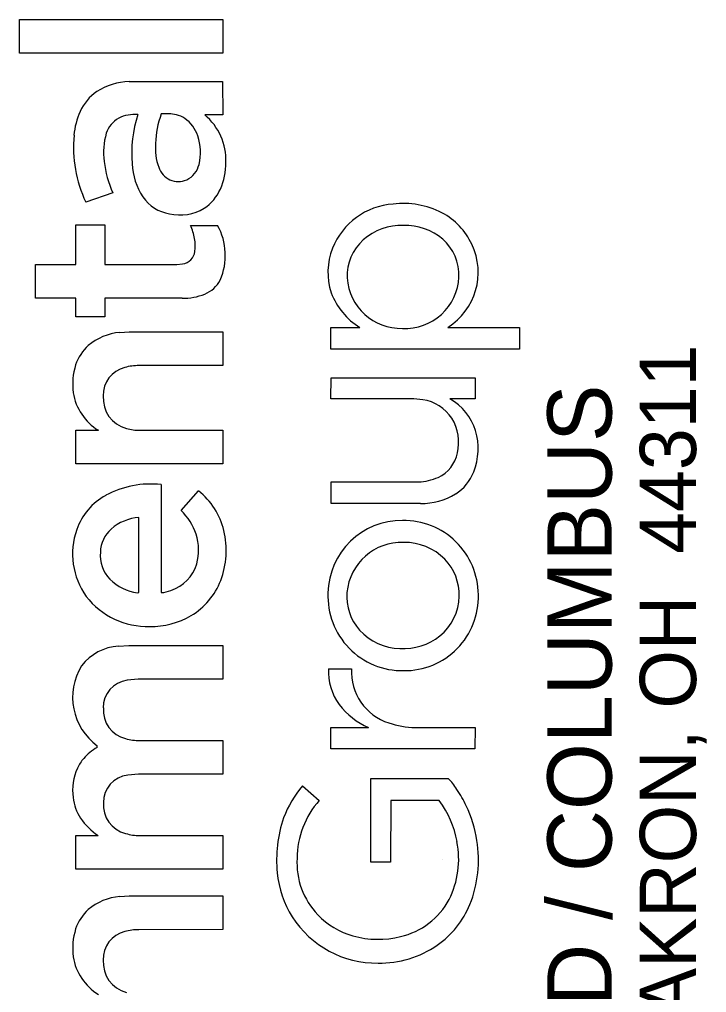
# Model space of a CAD drawing. Extents: x -0.2 to 34, y 0 to 22.
# Drawn here: x 32.376 to 32.984, y 3.882 to 4.744 of the extents above; entities that cross this region are included whole.
import ezdxf

# ---------------------------------------------------------------- set-up
doc = ezdxf.new("R2010")
doc.units = 0
doc.layers.add('RW_X_Esmt_SH', color=7, linetype='Continuous')

msp = doc.modelspace()

# ---------------------------------------------------------------- linework, layer by layer
at = {"layer": 'RW_X_Esmt_SH'}
for p, q in [((32.37557, 4.71411), (32.37557, 4.74397)), ((32.37557, 4.74397), (32.55571, 4.74397)), ((32.55571, 4.74397), (32.55571, 4.71411)), ((32.55571, 4.71411), (32.37557, 4.71411)), ((32.47265, 4.68899), (32.55553, 4.68918)), ((32.55553, 4.68918), (32.55571, 4.65956)), ((32.55571, 4.65956), (32.53971, 4.65956)), ((32.45818, 4.59045), (32.43431, 4.58233)), ((32.42542, 4.52705), (32.42548, 4.56209)), ((32.42548, 4.56209), (32.45108, 4.56209)), ((32.45108, 4.56209), (32.45117, 4.52705)), ((32.52695, 4.56159), (32.5511, 4.56159)), ((32.38964, 4.52701), (32.42542, 4.52705)), ((32.38964, 4.49719), (32.38964, 4.52701)), ((32.45117, 4.52705), (32.51498, 4.52705)), ((32.51498, 4.52705), (32.52005, 4.52749)), ((32.42542, 4.49717), (32.38964, 4.49719)), ((32.42542, 4.48067), (32.42542, 4.49717)), ((32.51969, 4.49718), (32.45108, 4.49715)), ((32.45108, 4.49715), (32.45108, 4.48066)), ((32.45108, 4.48066), (32.42542, 4.48067)), ((32.46439, 4.46686), (32.47289, 4.46732)), ((32.47289, 4.46732), (32.55571, 4.46732)), ((32.55571, 4.46732), (32.55571, 4.43753)), ((32.65152, 4.47113), (32.67709, 4.47115)), ((32.65152, 4.45215), (32.65152, 4.47113)), ((32.75491, 4.47132), (32.81858, 4.47108)), ((32.81858, 4.47108), (32.81843, 4.45215)), ((32.81843, 4.45215), (32.65152, 4.45215)), ((32.55571, 4.43753), (32.4814, 4.43746)), ((32.65152, 4.40801), (32.65153, 4.42672)), ((32.65153, 4.42672), (32.7791, 4.42664)), ((32.7791, 4.42664), (32.77908, 4.40796)), ((32.7249, 4.40796), (32.65152, 4.40801)), ((32.7328, 4.40727), (32.7249, 4.40796)), ((32.77908, 4.40796), (32.75689, 4.40796)), ((32.42542, 4.38016), (32.44552, 4.38021)), ((32.42542, 4.35035), (32.42542, 4.38016)), ((32.48222, 4.38021), (32.55569, 4.38021)), ((32.55569, 4.38021), (32.55571, 4.35045)), ((32.55571, 4.35045), (32.42542, 4.35035)), ((32.65154, 4.33443), (32.72905, 4.3345)), ((32.65165, 4.31543), (32.65154, 4.33443)), ((32.50108, 4.33209), (32.50118, 4.23657)), ((32.51882, 4.30927), (32.53422, 4.32662)), ((32.73073, 4.31543), (32.65165, 4.31543)), ((32.48144, 4.23644), (32.48144, 4.30296)), ((32.48016, 4.23628), (32.48144, 4.23644)), ((32.46329, 4.18915), (32.47259, 4.18968)), ((32.47259, 4.18968), (32.55557, 4.18968)), ((32.55557, 4.18968), (32.55571, 4.15982)), ((32.64932, 4.16907), (32.66978, 4.16907)), ((32.48058, 4.15981), (32.47102, 4.15881)), ((32.55571, 4.15982), (32.48058, 4.15981)), ((32.65152, 4.11699), (32.68476, 4.117)), ((32.65152, 4.098), (32.65152, 4.11699)), ((32.72605, 4.11703), (32.7791, 4.11696)), ((32.7791, 4.11696), (32.77903, 4.098)), ((32.48218, 4.10553), (32.55571, 4.10548)), ((32.55571, 4.10548), (32.55571, 4.07568)), ((32.44443, 4.09922), (32.44455, 4.10072)), ((32.77903, 4.098), (32.65152, 4.098)), ((32.4809, 4.07567), (32.47143, 4.07474)), ((32.55571, 4.07568), (32.4809, 4.07567)), ((32.6868, 4.07185), (32.75516, 4.07192)), ((32.6868, 3.99778), (32.6868, 4.07185)), ((32.62636, 4.06548), (32.64114, 4.05241)), ((32.70448, 4.05241), (32.70432, 3.99775)), ((32.74737, 4.05227), (32.70448, 4.05241)), ((32.42542, 3.99152), (32.42545, 4.02138)), ((32.42545, 4.02138), (32.44515, 4.02138)), ((32.48206, 4.02138), (32.55571, 4.02136)), ((32.55571, 4.02136), (32.55571, 3.99156)), ((32.75, 4), (32.75, 4)), ((32.55571, 3.99156), (32.42542, 3.99152)), ((32.70432, 3.99775), (32.6868, 3.99778)), ((32.46439, 3.96736), (32.47289, 3.96783)), ((32.47289, 3.96783), (32.55571, 3.96783)), ((32.55571, 3.96783), (32.55571, 3.93804)), ((32.55571, 3.93804), (32.4814, 3.93796))]:
    msp.add_line(p, q, dxfattribs=at)
msp.add_lwpolyline([(32.37557, 4.71411), (32.37557, 4.74397), (32.55571, 4.74397), (32.55571, 4.71411)], close=True, dxfattribs=at)
for points in [[(32.47265, 4.68899), (32.55553, 4.68918), (32.55571, 4.65956)], [(32.55571, 4.65956), (32.53971, 4.65956)], [(32.45818, 4.59045), (32.43431, 4.58233)], [(32.51969, 4.49718), (32.45108, 4.49715), (32.45108, 4.48066), (32.42542, 4.48067), (32.42542, 4.49717), (32.38964, 4.49719), (32.38964, 4.52701), (32.42542, 4.52705), (32.42548, 4.56209), (32.45108, 4.56209), (32.45117, 4.52705), (32.51498, 4.52705), (32.52005, 4.52749)], [(32.52695, 4.56159), (32.5511, 4.56159)], [(32.46439, 4.46686), (32.47289, 4.46732), (32.55571, 4.46732), (32.55571, 4.43753), (32.4814, 4.43746)], [(32.75491, 4.47132), (32.81858, 4.47108), (32.81843, 4.45215), (32.65152, 4.45215)], [(32.65152, 4.45215), (32.65152, 4.47113), (32.67709, 4.47115)], [(32.7328, 4.40727), (32.7249, 4.40796), (32.65152, 4.40801), (32.65153, 4.42672), (32.7791, 4.42664), (32.77908, 4.40796), (32.75689, 4.40796)], [(32.42542, 4.35035), (32.42542, 4.38016), (32.44552, 4.38021)], [(32.48222, 4.38021), (32.55569, 4.38021), (32.55571, 4.35045), (32.42542, 4.35035)], [(32.73073, 4.31543), (32.65165, 4.31543), (32.65154, 4.33443), (32.72905, 4.3345)], [(32.50108, 4.33209), (32.50118, 4.23657)], [(32.51882, 4.30927), (32.53422, 4.32662)], [(32.48016, 4.23628), (32.48144, 4.23644), (32.48144, 4.30296)], [(32.46329, 4.18915), (32.47259, 4.18968), (32.55557, 4.18968), (32.55571, 4.15982), (32.48058, 4.15981), (32.47102, 4.15881)], [(32.64932, 4.16907), (32.66978, 4.16907)], [(32.72605, 4.11703), (32.7791, 4.11696), (32.77903, 4.098), (32.65152, 4.098)], [(32.65152, 4.098), (32.65152, 4.11699), (32.68476, 4.117)], [(32.48218, 4.10553), (32.55571, 4.10548), (32.55571, 4.07568), (32.4809, 4.07567), (32.47143, 4.07474)], [(32.44443, 4.09922), (32.44455, 4.10072)], [(32.74737, 4.05227), (32.70448, 4.05241), (32.70432, 3.99775), (32.6868, 3.99778), (32.6868, 4.07185), (32.75516, 4.07192)], [(32.62636, 4.06548), (32.64114, 4.05241)], [(32.42542, 3.99152), (32.42545, 4.02138), (32.44515, 4.02138)], [(32.48206, 4.02138), (32.55571, 4.02136), (32.55571, 3.99156), (32.42542, 3.99152)], [(32.46439, 3.96736), (32.47289, 3.96783), (32.55571, 3.96783), (32.55571, 3.93804), (32.4814, 3.93796)]]:
    msp.add_lwpolyline(points, dxfattribs=at)
for centre, radius, start, end in [((32.47452, 4.63256), 0.05646, 91.89422, 122.63175), ((32.47452, 4.63256), 0.05646, 91.89422, 122.63175), ((32.46847, 4.64467), 0.04302, 124.53704, 155.65938), ((32.46847, 4.64467), 0.04302, 124.53704, 155.65938), ((32.48824, 4.63612), 0.06457, 155.9764, 175.31491), ((32.48824, 4.63612), 0.06457, 155.9764, 175.31491), ((32.47525, 4.6356), 0.024, 119.42515, 161.66285), ((32.47525, 4.6356), 0.024, 119.42515, 161.66285), ((32.47786, 4.62778), 0.03213, 85.38017, 116.62224), ((32.47786, 4.62778), 0.03213, 85.38017, 116.62224), ((32.58787, 4.62508), 0.1129, 162.08213, 184.52847), ((32.58787, 4.62508), 0.1129, 162.08213, 184.52847), ((32.58013, 4.63131), 0.08411, 159.83657, 178.03621), ((32.58013, 4.63131), 0.08411, 159.83657, 178.03621), ((32.50509, 4.60743), 0.05302, 79.66963, 94.23216), ((32.50509, 4.60743), 0.05302, 79.66963, 94.23216), ((32.50892, 4.63643), 0.02384, 56.89129, 76.21489), ((32.50892, 4.63643), 0.02384, 56.89129, 76.21489), ((32.5052, 4.63184), 0.02973, 17.59837, 55.72819), ((32.5052, 4.63184), 0.02973, 17.59837, 55.72819), ((32.50551, 4.61914), 0.05295, 358.07459, 49.76196), ((32.50551, 4.61914), 0.05295, 358.07459, 49.76196), ((32.53639, 4.63078), 0.113, 174.61011, 205.38987), ((32.53639, 4.63078), 0.113, 174.61011, 205.38987), ((32.50758, 4.62645), 0.05758, 163.13694, 188.16749), ((32.50758, 4.62645), 0.05758, 163.13694, 188.16749), ((32.4916, 4.6264), 0.04435, 345.94084, 18.99188), ((32.4916, 4.6264), 0.04435, 345.94084, 18.99188), ((32.54655, 4.6303), 0.05063, 175.59026, 199.88569), ((32.54655, 4.6303), 0.05063, 175.59026, 199.88569), ((32.54725, 4.62973), 0.09735, 186.75982, 203.79807), ((32.54725, 4.62973), 0.09735, 186.75982, 203.79807), ((32.53279, 4.61874), 0.05752, 182.56764, 213.71437), ((32.53279, 4.61874), 0.05752, 182.56764, 213.71437), ((32.51642, 4.61886), 0.01841, 198.28436, 293.30806), ((32.51642, 4.61886), 0.01841, 198.28436, 293.30806), ((32.51521, 4.61994), 0.01989, 295.28829, 347.46387), ((32.51521, 4.61994), 0.01989, 295.28829, 347.46387), ((32.50187, 4.61678), 0.05657, 336.01604, 0.59505), ((32.50187, 4.61678), 0.05657, 336.01604, 0.59505), ((32.51752, 4.60969), 0.03938, 303.44357, 336.18), ((32.51752, 4.60969), 0.03938, 303.44357, 336.18), ((32.51487, 4.60782), 0.03656, 215.06685, 259.81327), ((32.51487, 4.60782), 0.03656, 215.06685, 259.81327), ((32.51753, 4.6131), 0.04227, 257.52557, 300.88195), ((32.51753, 4.6131), 0.04227, 257.52557, 300.88195), ((32.71081, 4.51825), 0.06243, 93.98662, 158.31194), ((32.71081, 4.51825), 0.06243, 93.98662, 158.31194), ((32.71557, 4.5065), 0.07459, 62.68889, 97.01346), ((32.71557, 4.5065), 0.07459, 62.68889, 97.01346), ((32.72123, 4.51914), 0.06076, 25.06574, 61.96022), ((32.72123, 4.51914), 0.06076, 25.06574, 61.96022), ((32.48625, 4.54199), 0.04518, 10.15449, 25.72303), ((32.48625, 4.54199), 0.04518, 10.15449, 25.72303), ((32.50302, 4.53506), 0.05491, 336.58903, 28.89913), ((32.50302, 4.53506), 0.05491, 336.58903, 28.89913), ((32.71379, 4.51017), 0.05134, 87.89653, 131.18123), ((32.71379, 4.51017), 0.05134, 87.89653, 131.18123), ((32.7175, 4.51023), 0.05127, 49.90886, 92.03625), ((32.7175, 4.51023), 0.05127, 49.90886, 92.03625), ((32.49573, 4.54365), 0.03556, 351.91398, 10.20594), ((32.49573, 4.54365), 0.03556, 351.91398, 10.20594), ((32.70695, 4.52016), 0.05815, 158.65601, 198.17101), ((32.70695, 4.52016), 0.05815, 158.65601, 198.17101), ((32.7092, 4.51674), 0.04338, 132.32887, 182.09489), ((32.7092, 4.51674), 0.04338, 132.32887, 182.09489), ((32.72154, 4.51733), 0.04327, 358.04871, 47.94467), ((32.72154, 4.51733), 0.04327, 358.04871, 47.94467), ((32.7245, 4.52004), 0.05743, 301.97764, 25.64176), ((32.7245, 4.52004), 0.05743, 301.97764, 25.64176), ((32.51837, 4.54001), 0.01263, 277.61423, 353.79181), ((32.51837, 4.54001), 0.01263, 277.61423, 353.79181), ((32.71352, 4.51815), 0.04776, 183.59741, 271.7045), ((32.71352, 4.51815), 0.04776, 183.59741, 271.7045), ((32.71717, 4.51801), 0.04766, 267.31494, 357.4019), ((32.71717, 4.51801), 0.04766, 267.31494, 357.4019), ((32.52913, 4.52612), 0.02749, 292.68889, 332.05977), ((32.52913, 4.52612), 0.02749, 292.68889, 332.05977), ((32.52088, 4.54856), 0.05139, 268.67266, 291.52354), ((32.52088, 4.54856), 0.05139, 268.67266, 291.52354), ((32.7103, 4.52433), 0.0627, 200.83985, 238.01619), ((32.7103, 4.52433), 0.0627, 200.83985, 238.01619), ((32.46871, 4.41716), 0.04988, 94.97056, 130.22484), ((32.46871, 4.41716), 0.04988, 94.97056, 130.22484), ((32.46348, 4.42551), 0.04016, 132.22383, 161.68229), ((32.46348, 4.42551), 0.04016, 132.22383, 161.68229), ((32.47872, 4.42108), 0.05602, 162.27398, 187.79173), ((32.47872, 4.42108), 0.05602, 162.27398, 187.79173), ((32.48108, 4.39145), 0.04601, 89.60515, 105.33026), ((32.48108, 4.39145), 0.04601, 89.60515, 105.33026), ((32.47482, 4.41155), 0.02498, 103.68683, 182.21395), ((32.47482, 4.41155), 0.02498, 103.68683, 182.21395), ((32.47027, 4.4209), 0.04763, 188.96462, 238.69865), ((32.47027, 4.4209), 0.04763, 188.96462, 238.69865), ((32.47735, 4.40846), 0.02757, 175.58441, 255.13816), ((32.47735, 4.40846), 0.02757, 175.58441, 255.13816), ((32.72711, 4.36998), 0.03772, 33.50082, 81.32954), ((32.72711, 4.36998), 0.03772, 33.50082, 81.32954), ((32.73239, 4.36485), 0.04959, 17.62209, 60.38974), ((32.73239, 4.36485), 0.04959, 17.62209, 60.38974), ((32.72414, 4.3695), 0.04048, 346.56179, 31.75389), ((32.72414, 4.3695), 0.04048, 346.56179, 31.75389), ((32.48183, 4.42235), 0.04215, 254.08913, 270.52838), ((32.48183, 4.42235), 0.04215, 254.08913, 270.52838), ((32.72343, 4.36415), 0.05838, 339.16197, 15.61485), ((32.72343, 4.36415), 0.05838, 339.16197, 15.61485), ((32.73371, 4.36616), 0.03042, 294.63214, 348.48625), ((32.73371, 4.36616), 0.03042, 294.63214, 348.48625), ((32.739, 4.35901), 0.04201, 303.10391, 338.15613), ((32.739, 4.35901), 0.04201, 303.10391, 338.15613), ((32.72747, 4.38081), 0.04633, 271.95199, 294.08943), ((32.72747, 4.38081), 0.04633, 271.95199, 294.08943), ((32.49176, 4.24874), 0.08387, 83.62118, 118.28448), ((32.49176, 4.24874), 0.08387, 83.62118, 118.28448), ((32.49399, 4.2763), 0.06443, 13.53275, 51.36266), ((32.49399, 4.2763), 0.06443, 13.53275, 51.36266), ((32.47894, 4.27368), 0.05583, 118.82935, 160.62242), ((32.47894, 4.27368), 0.05583, 118.82935, 160.62242), ((32.7321, 4.37256), 0.05715, 268.62699, 301.47779), ((32.7321, 4.37256), 0.05715, 268.62699, 301.47779), ((32.48033, 4.27018), 0.05485, 19.0387, 45.44322), ((32.48033, 4.27018), 0.05485, 19.0387, 45.44322), ((32.4844, 4.26071), 0.04236, 94.01311, 130.88062), ((32.4844, 4.26071), 0.04236, 94.01311, 130.88062), ((32.71435, 4.23484), 0.06552, 89.48213, 178.77752), ((32.71435, 4.23484), 0.06552, 89.48213, 178.77752), ((32.71582, 4.23414), 0.06623, 0.42265, 90.7613), ((32.71582, 4.23414), 0.06623, 0.42265, 90.7613), ((32.48697, 4.27074), 0.06438, 160.52138, 215.78155), ((32.48697, 4.27074), 0.06438, 160.52138, 215.78155), ((32.47703, 4.2709), 0.02985, 132.98553, 177.1802), ((32.47703, 4.2709), 0.02985, 132.98553, 177.1802), ((32.48289, 4.27384), 0.0758, 339.35431, 13.37708), ((32.48289, 4.27384), 0.0758, 339.35431, 13.37708), ((32.48724, 4.27433), 0.04701, 344.60723, 17.00675), ((32.48724, 4.27433), 0.04701, 344.60723, 17.00675), ((32.71397, 4.23244), 0.04846, 87.68827, 175.01696), ((32.71397, 4.23244), 0.04846, 87.68827, 175.01696), ((32.71659, 4.23036), 0.05052, 44.91202, 90.75914), ((32.71659, 4.23036), 0.05052, 44.91202, 90.75914), ((32.47824, 4.26966), 0.03114, 175.00138, 223.2876), ((32.47824, 4.26966), 0.03114, 175.00138, 223.2876), ((32.71955, 4.23452), 0.04549, 358.32279, 43.83486), ((32.71955, 4.23452), 0.04549, 358.32279, 43.83486), ((32.49895, 4.27177), 0.03504, 288.01084, 343.55364), ((32.49895, 4.27177), 0.03504, 288.01084, 343.55364), ((32.48546, 4.27826), 0.04232, 225.06454, 262.79701), ((32.48546, 4.27826), 0.04232, 225.06454, 262.79701), ((32.49548, 4.26982), 0.0626, 300.94393, 338.73223), ((32.49548, 4.26982), 0.0626, 300.94393, 338.73223), ((32.48908, 4.27516), 0.06872, 217.74341, 271.65606), ((32.48908, 4.27516), 0.06872, 217.74341, 271.65606), ((32.50129, 4.25678), 0.02021, 269.70042, 294.87295), ((32.50129, 4.25678), 0.02021, 269.70042, 294.87295), ((32.71483, 4.2334), 0.06606, 177.53728, 270.94524), ((32.71483, 4.2334), 0.06606, 177.53728, 270.94524), ((32.71085, 4.23311), 0.0453, 175.51467, 221.42047), ((32.71085, 4.23311), 0.0453, 175.51467, 221.42047), ((32.71671, 4.23271), 0.06536, 269.30834, 1.67905), ((32.71671, 4.23271), 0.06536, 269.30834, 1.67905), ((32.71931, 4.23374), 0.04572, 308.90382, 359.30947), ((32.71931, 4.23374), 0.04572, 308.90382, 359.30947), ((32.49204, 4.27702), 0.07055, 269.20529, 300.33566), ((32.49204, 4.27702), 0.07055, 269.20529, 300.33566), ((32.71399, 4.23734), 0.05046, 222.66255, 268.37331), ((32.71399, 4.23734), 0.05046, 222.66255, 268.37331), ((32.71567, 4.23859), 0.05178, 266.55312, 308.67253), ((32.71567, 4.23859), 0.05178, 266.55312, 308.67253), ((32.46638, 4.14404), 0.04521, 93.91118, 142.30723), ((32.46638, 4.14404), 0.04521, 93.91118, 142.30723), ((32.47585, 4.14373), 0.05319, 148.28793, 233.9556), ((32.47585, 4.14373), 0.05319, 148.28793, 233.9556), ((32.69878, 4.16662), 0.04952, 177.16211, 216.28024), ((32.69878, 4.16662), 0.04952, 177.16211, 216.28024), ((32.71735, 4.16638), 0.04764, 176.76988, 252.15044), ((32.71735, 4.16638), 0.04764, 176.76988, 252.15044), ((32.47384, 4.13499), 0.02399, 96.75763, 181.6251), ((32.47384, 4.13499), 0.02399, 96.75763, 181.6251), ((32.70975, 4.17555), 0.06366, 216.91526, 246.88619), ((32.70975, 4.17555), 0.06366, 216.91526, 246.88619), ((32.47577, 4.13241), 0.02597, 175.81573, 256.16716), ((32.47577, 4.13241), 0.02597, 175.81573, 256.16716), ((32.7269, 4.19175), 0.07473, 251.13884, 269.34694), ((32.7269, 4.19175), 0.07473, 251.13884, 269.34694), ((32.4817, 4.15053), 0.04501, 254.34629, 270.61033), ((32.4817, 4.15053), 0.04501, 254.34629, 270.61033), ((32.4638, 4.06267), 0.04137, 117.91625, 139.24296), ((32.4638, 4.06267), 0.04137, 117.91625, 139.24296), ((32.46194, 4.06452), 0.03875, 139.52447, 154.84698), ((32.46194, 4.06452), 0.03875, 139.52447, 154.84698), ((32.47144, 4.0612), 0.04877, 156.06382, 187.3493), ((32.47144, 4.0612), 0.04877, 156.06382, 187.3493), ((32.47421, 4.05056), 0.02434, 96.5532, 179.94902), ((32.47421, 4.05056), 0.02434, 96.5532, 179.94902), ((32.72498, 4.03937), 0.04438, 30.98913, 47.16099), ((32.72498, 4.03937), 0.04438, 30.98913, 47.16099), ((32.70163, 4.00187), 0.09855, 139.79476, 159.13696), ((32.70163, 4.00187), 0.09855, 139.79476, 159.13696), ((32.67091, 4.00018), 0.11106, 25.30315, 33.96179), ((32.67091, 4.00018), 0.11106, 25.30315, 33.96179), ((32.46461, 4.05974), 0.04181, 186.5579, 213.38846), ((32.46461, 4.05974), 0.04181, 186.5579, 213.38846), ((32.47608, 4.04863), 0.02628, 175.722, 255.78627), ((32.47608, 4.04863), 0.02628, 175.722, 255.78627), ((32.69899, 4.00079), 0.07753, 138.25804, 179.70064), ((32.69899, 4.00079), 0.07753, 138.25804, 179.70064), ((32.67889, 4.00099), 0.08556, 10.07509, 36.83189), ((32.67889, 4.00099), 0.08556, 10.07509, 36.83189), ((32.6704, 3.99987), 0.11166, 8.80339, 25.33484), ((32.6704, 3.99987), 0.11166, 8.80339, 25.33484), ((32.47886, 4.07078), 0.0598, 214.70433, 235.68724), ((32.47886, 4.07078), 0.0598, 214.70433, 235.68724), ((32.7187, 3.99968), 0.11536, 161.14379, 185.62812), ((32.7187, 3.99968), 0.11536, 161.14379, 185.62812), ((32.48195, 4.06518), 0.0438, 253.66719, 270.14979), ((32.48195, 4.06518), 0.0438, 253.66719, 270.14979), ((32.68425, 4.00057), 0.08036, 333.46689, 11.03668), ((32.68425, 4.00057), 0.08036, 333.46689, 11.03668), ((32.67564, 3.99977), 0.10649, 338.28866, 9.28548), ((32.67564, 3.99977), 0.10649, 338.28866, 9.28548), ((32.68811, 3.99732), 0.06676, 176.66577, 223.6912), ((32.68811, 3.99732), 0.06676, 176.66577, 223.6912), ((32.69336, 3.99699), 0.08987, 185.50773, 212.01294), ((32.69336, 3.99699), 0.08987, 185.50773, 212.01294), ((32.46871, 3.91767), 0.04988, 94.97056, 130.22484), ((32.46871, 3.91767), 0.04988, 94.97056, 130.22484), ((32.69868, 3.99547), 0.0652, 282.88151, 331.81475), ((32.69868, 3.99547), 0.0652, 282.88151, 331.81475), ((32.46348, 3.92602), 0.04016, 132.22383, 161.68229), ((32.46348, 3.92602), 0.04016, 132.22383, 161.68229), ((32.69835, 3.99168), 0.08241, 305.03061, 337.67573), ((32.69835, 3.99168), 0.08241, 305.03061, 337.67573), ((32.69211, 3.99748), 0.08908, 212.70222, 270.71399), ((32.69211, 3.99748), 0.08908, 212.70222, 270.71399), ((32.69045, 4.00011), 0.07039, 224.02147, 253.88), ((32.69045, 4.00011), 0.07039, 224.02147, 253.88), ((32.47872, 3.92158), 0.05602, 162.27398, 187.79173), ((32.47872, 3.92158), 0.05602, 162.27398, 187.79173), ((32.48108, 3.89196), 0.04601, 89.60515, 105.33026), ((32.48108, 3.89196), 0.04601, 89.60515, 105.33026), ((32.47482, 3.91206), 0.02498, 103.68683, 182.21395), ((32.47482, 3.91206), 0.02498, 103.68683, 182.21395), ((32.69318, 4.01254), 0.08309, 254.45353, 283.9512), ((32.69318, 4.01254), 0.08309, 254.45353, 283.9512), ((32.69429, 3.99979), 0.09138, 269.3273, 304.19632), ((32.69429, 3.99979), 0.09138, 269.3273, 304.19632), ((32.47027, 3.92141), 0.04763, 188.96462, 238.69865), ((32.47027, 3.92141), 0.04763, 188.96462, 238.69865), ((32.47735, 3.90897), 0.02757, 175.58441, 255.13816), ((32.47735, 3.90897), 0.02757, 175.58441, 255.13816)]:
    msp.add_arc(centre, radius, start, end, dxfattribs=at)

# ---------------------------------------------------------------- texts
for s, height, p in [('450 GRANT ST., AKRON, OH  44311', 0.0498462, (32.97489, 3.33738)), ('AKRON / CLEVELAND / COLUMBUS', 0.056969, (32.90012, 3.138))]:
    msp.add_text(s, height=height, rotation=90, dxfattribs=at).set_placement(p)

doc.saveas('drawing.dxf')
